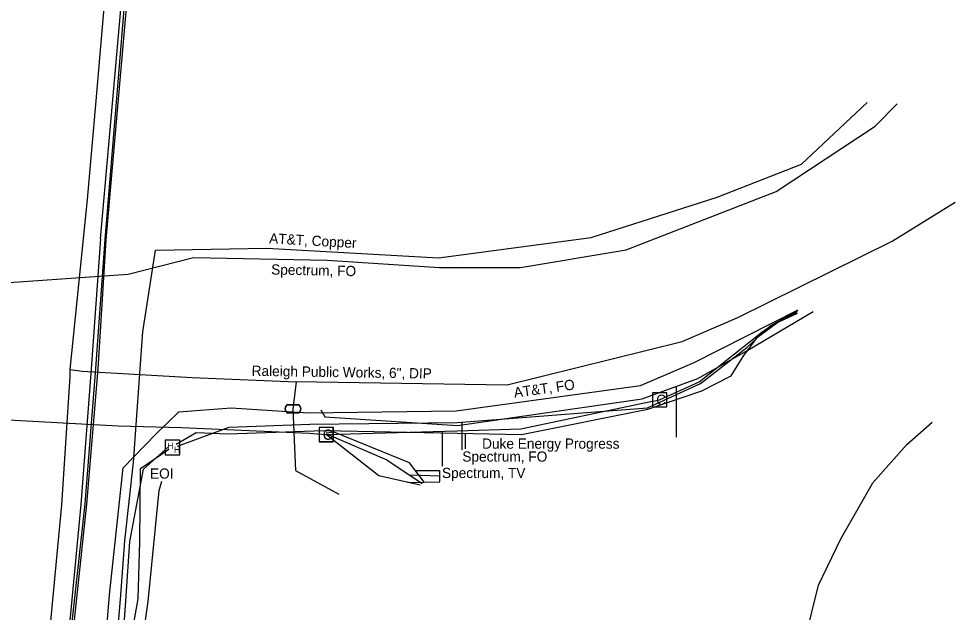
# Model space of a CAD drawing. Extents: x 2070721 to 2083039, y 729290 to 737883.
# Drawn here: x 2082364.3 to 2082731.1, y 736466.5 to 736699 of the extents above; entities that cross this region are included whole.
import ezdxf

# ---------------------------------------------------------------- set-up
doc = ezdxf.new("R2010")
doc.units = 0
for name, color, linetype in [('Cogo Default Point CELL', 7, 'Continuous'), ('Exist Utilities Gas UG Line SUE Cogo Point CELL', 7, 'Continuous'), ('Exist Utilities Gas UG Line SUE LOS B Cogo Comment', 7, 'Continuous'), ('Exist Utilities Gas UG Line SUE LOS B Cogo Number', 7, 'Continuous'), ('Exist Utilities Gas UG Line SUE LOS B Cogo Point CELL', 7, 'Continuous'), ('Exist Utilities Gas Valve CELL', 7, 'Continuous'), ('Exist Utilities Power Pole CELL', 7, 'Continuous'), ('Exist Utilities Telephone Hand Hole Cogo Elevation', 7, 'Continuous'), ('Exist Utilities Telephone Pedestal CELL', 7, 'Continuous'), ('Exist Utilities Telephone UG Cable Cogo Point CELL', 7, 'Continuous'), ('Exist Utilities Telephone UG Cable SUE LOS C Cogo Comment', 7, 'Continuous'), ('Exist Utilities Telephone UG FO Cogo Point CELL', 7, 'Continuous'), ('Exist Utilities TV Pedestal CELL', 7, 'Continuous'), ('Exist Utilities TV Pedestal Cogo Elevation', 7, 'Continuous'), ('Exist Utilities TV UG Cable Cogo Point CELL', 7, 'Continuous'), ('Exist Utilities TV UG Cable SUE LOS C Cogo Comment', 7, 'Continuous'), ('Exist Utilities TV UG Cable SUE LOS C Cogo Elevation', 7, 'Continuous'), ('Exist Utilities TV UG Cable SUE LOS C Cogo Point CELL', 7, 'Continuous'), ('Exist Utilities Water Manhole CELL', 7, 'Continuous'), ('Exist Utilities Water Meter CELL', 7, 'Continuous'), ('Exist Utilities Water Meter Cogo Number', 7, 'Continuous'), ('Exist Utilities Water UG Line SUE LOS B Cogo Elevation', 7, 'Continuous')]:
    doc.layers.add(name, color=color, linetype=linetype)

msp = doc.modelspace()

# ---------------------------------------------------------------- linework, layer by layer
at = {"layer": 'Cogo Default Point CELL'}
for p, q in [((2082615.26, 736549.71), (2082615.26, 736549.71)), ((2082484.65, 736536.03), (2082484.65, 736536.03)), ((2082484.7, 736536.09), (2082484.7, 736536.09))]:
    msp.add_line(p, q, dxfattribs=at)
for points in [[(2082612.49, 736546.94), (2082618.04, 736546.94), (2082618.04, 736552.48), (2082612.49, 736552.48), (2082612.49, 736546.94)], [(2082481.88, 736533.26), (2082487.43, 736533.26), (2082487.43, 736538.81), (2082481.88, 736538.81), (2082481.88, 736533.26)], [(2082481.93, 736533.32), (2082487.48, 736533.32), (2082487.48, 736538.86), (2082481.93, 736538.86), (2082481.93, 736533.32)]]:
    msp.add_lwpolyline(points, dxfattribs=at)
at = {"layer": 'Exist Utilities Gas UG Line SUE LOS B Cogo Number'}
for p, q in [((2082537.8, 736540.94), (2082537.8, 736530.14)), ((2082539.08, 736536.51), (2082539.08, 736530.49))]:
    msp.add_line(p, q, dxfattribs=at)
at = {"layer": 'Exist Utilities Gas Valve CELL'}
msp.add_line((2082621.8, 736554.96), (2082621.8, 736535.09), dxfattribs=at)
at = {"layer": 'Exist Utilities Power Pole CELL'}
for points in [[(2082396.3, 736612.75), (2082410.09, 736769.04), (2082413.73, 736812.06), (2082415.9, 736838.6), (2082420.43, 736883.01), (2082426.83, 736940.19), (2082430.34, 736980.56), (2082434.54, 737015.35), (2082440.98, 737055.09)], [(2082398.47, 736612.36), (2082412.17, 736768.95), (2082414.49, 736785.54), (2082418.32, 736838.61), (2082422.49, 736882.86), (2082432.87, 736980.11), (2082434.6, 737016.15), (2082441.99, 737054.65)], [(2082396.3, 736612.75), (2082392.62, 736561.83), (2082388.6, 736508.73), (2082382.17, 736441.21), (2082376.53, 736380.02), (2082370.92, 736297.49), (2082367.41, 736251.8), (2082369.98, 736249.96), (2082368.85, 736250.78)], [(2082370.04, 736251.07), (2082373.38, 736297.59), (2082378.96, 736379.81), (2082383.81, 736441.35), (2082390.88, 736508.81), (2082395.35, 736561.8), (2082398.47, 736612.36)]]:
    msp.add_lwpolyline(points, dxfattribs=at)
at = {"layer": 'Exist Utilities Telephone UG Cable Cogo Point CELL'}
msp.add_line((2082424.54, 736531.03), (2082424.54, 736531.03), dxfattribs=at)
msp.add_lwpolyline([(2082421.67, 736528.16), (2082427.42, 736528.16), (2082427.42, 736533.91), (2082421.67, 736533.91), (2082421.67, 736528.16)], dxfattribs=at)
at = {"layer": 'Exist Utilities Telephone UG Cable SUE LOS C Cogo Comment'}
msp.add_lwpolyline([(2082395.72, 736292.86), (2082399.83, 736311.96), (2082400.03, 736311.89), (2082404.85, 736370.66), (2082409.06, 736429.49), (2082414.93, 736470.65), (2082419.29, 736514.19), (2082420.3, 736517.77)], dxfattribs=at)
at = {"layer": 'Exist Utilities Telephone UG FO Cogo Point CELL'}
msp.add_line((2082471.67, 736546.21), (2082471.67, 736546.21), dxfattribs=at)
for points in [[(2082469.63, 736547.91), (2082473.71, 736547.91)], [(2082469.63, 736547.77), (2082473.71, 736547.77)], [(2082473.71, 736544.65), (2082469.61, 736544.65)], [(2082473.71, 736544.51), (2082469.61, 736544.51)]]:
    msp.add_lwpolyline(points, dxfattribs=at)
for centre, radius, start, end in [((2082470.36, 736546.2), 1.86, 113.178, 245.9794), ((2082470.37, 736546.2), 1.73, 115.3009, 243.7824), ((2082472.96, 736546.21), 1.86, 293.6483, 66.3084), ((2082472.97, 736546.21), 1.73, 295.1272, 64.8728)]:
    msp.add_arc(centre, radius, start, end, dxfattribs=at)
at = {"layer": 'Exist Utilities TV Pedestal CELL'}
for points in [[(2082425.9, 736532.27), (2082433.71, 736536.84), (2082446.22, 736536.42), (2082483.71, 736537.72), (2082535.95, 736536.62), (2082561.21, 736536.1), (2082610.64, 736546), (2082631.79, 736553.16), (2082643.29, 736559.15), (2082648.05, 736566.62), (2082653.66, 736574.26), (2082661.61, 736580.11), (2082669.14, 736584.07)], [(2082426.4, 736531.55), (2082446.63, 736539.04), (2082478.25, 736540.13), (2082535.97, 736540.82), (2082610.47, 736546.5), (2082631.23, 736556.05), (2082649.4, 736570.19), (2082658.63, 736578.68), (2082669.27, 736583.69)], [(2082383.39, 736263.77), (2082384.87, 736281.05), (2082388.71, 736311.38), (2082396.25, 736370.54), (2082403.33, 736430.4), (2082406.33, 736472.77), (2082407.72, 736494.25), (2082413.13, 736522.51), (2082423.07, 736531.36)], [(2082385.03, 736263.7), (2082391.12, 736281.95), (2082396.82, 736312.11), (2082398.55, 736370.94), (2082403.55, 736430), (2082411.08, 736471.72), (2082411.73, 736494.17), (2082412, 736522.79), (2082423.09, 736530.34)]]:
    msp.add_lwpolyline(points, dxfattribs=at)
at = {"layer": 'Exist Utilities TV Pedestal Cogo Elevation'}
for points in [[(2082384.35, 736558.86), (2082384.46, 736561.59), (2082391.2, 736628.12), (2082394.55, 736666.82), (2082398.88, 736717.07), (2082400.72, 736736.91)], [(2082472.81, 736556.82), (2082555.61, 736555.54), (2082624.05, 736572.52), (2082645.91, 736581.87), (2082706.38, 736611.81), (2082731.06, 736627.13)], [(2082359.3, 736290.13), (2082359.45, 736292.32), (2082374.67, 736439.46), (2082381.09, 736508.57), (2082384.35, 736558.86)], [(2082384.46, 736561.59), (2082389.12, 736560.96), (2082432.21, 736558.41), (2082472.93, 736556.77)], [(2082472.93, 736556.77), (2082472.27, 736551.43), (2082471.61, 736546.09), (2082472.7, 736521.96), (2082489.65, 736512.8)]]:
    msp.add_lwpolyline(points, dxfattribs=at)
at = {"layer": 'Exist Utilities TV UG Cable Cogo Point CELL'}
msp.add_lwpolyline([(2082392.88, 736263.89), (2082382.27, 736265.88), (2082385.19, 736281.09), (2082389.11, 736311.29), (2082396.78, 736370.29), (2082400.63, 736429.15), (2082404.26, 736473.32), (2082405.87, 736494.42), (2082409.26, 736525.23), (2082412.82, 736576.27), (2082417.8, 736608.3), (2082461.47, 736609.04), (2082528.72, 736605.28), (2082588.4, 736613.3), (2082637.77, 736629.11), (2082670.84, 736641.95), (2082696.51, 736666.16)], dxfattribs=at)
at = {"layer": 'Exist Utilities TV UG Cable SUE LOS C Cogo Comment'}
for points in [[(2082482.56, 736545.79), (2082484.21, 736542.97), (2082536.06, 736539.61), (2082608.47, 736550.06), (2082630.23, 736558.05), (2082649.11, 736568.73), (2082675.35, 736584.3)], [(2082633.41, 736326.82), (2082635.39, 736331.76), (2082647.25, 736364.29), (2082654.64, 736387.64), (2082662.17, 736415.15), (2082677.46, 736477.1), (2082686.22, 736495.26), (2082698.83, 736517.21), (2082712.08, 736532.18), (2082721.96, 736540.93)]]:
    msp.add_lwpolyline(points, dxfattribs=at)
at = {"layer": 'Exist Utilities TV UG Cable SUE LOS C Cogo Elevation'}
for points in [[(2082346.94, 736593.86), (2082360.72, 736589.21), (2082357.72, 736541.97), (2082403.21, 736539.49), (2082428.03, 736538.87), (2082478.07, 736536.61), (2082484.59, 736536.15), (2082535.98, 736537.5), (2082560.91, 736538.33), (2082609.93, 736548.58), (2082615.28, 736549.68), (2082630.73, 736556.71), (2082655.26, 736576.14), (2082659.68, 736579.26), (2082669.26, 736584.45)], [(2082523.24, 736517.33), (2082517.33, 736525), (2082487.79, 736537.04), (2082484.69, 736536.67)], [(2082484.78, 736536.42), (2082508.4, 736526.14), (2082522.29, 736516.92)], [(2082521.51, 736516.25), (2082505.36, 736519.92), (2082484.78, 736536.03)]]:
    msp.add_lwpolyline(points, dxfattribs=at)
at = {"layer": 'Exist Utilities TV UG Cable SUE LOS C Cogo Point CELL'}
for points in [[(2082398.1, 736612.48), (2082411.1, 736769.26), (2082413.2, 736785.84), (2082417.08, 736838.79), (2082421.4, 736882.93), (2082431.06, 736980.24), (2082434.68, 737016.11), (2082441.24, 737055.15)], [(2082369.85, 736250.96), (2082372.63, 736297.63), (2082378.59, 736379.94), (2082382.86, 736441.28), (2082390.24, 736508.9), (2082394.52, 736561.91), (2082398.1, 736612.48)], [(2082380.42, 736270.25), (2082381.12, 736283.15), (2082384.63, 736311.5), (2082391.98, 736371.16), (2082396.29, 736430.22), (2082399.86, 736473.26), (2082405.23, 736523.1), (2082417.88, 736536.05), (2082427.03, 736545.03), (2082447.47, 736546.52), (2082477.66, 736544.64), (2082535.53, 736545.32), (2082607.76, 736555.33), (2082628.77, 736564.28), (2082669.56, 736584.92)]]:
    msp.add_lwpolyline(points, dxfattribs=at)
at = {"layer": 'Exist Utilities Water Manhole CELL'}
for p, q in [((2082530.08, 736537.27), (2082530.08, 736523.74)), ((2082519.78, 736522.06), (2082529.16, 736522.06))]:
    msp.add_line(p, q, dxfattribs=at)
for points in [[(2082517.8, 736520.25), (2082529.16, 736519.88), (2082529.16, 736522.04)], [(2082516.56, 736517.37), (2082529.16, 736517.56), (2082529.16, 736519.84)]]:
    msp.add_lwpolyline(points, dxfattribs=at)
at = {"layer": 'Exist Utilities Water UG Line SUE LOS B Cogo Elevation'}
msp.add_lwpolyline([(2082347.36, 736594.7), (2082407.12, 736598.92), (2082432.73, 736605.4), (2082485.1, 736604.34), (2082529.04, 736601.5), (2082560.83, 736601.5), (2082602.16, 736608.48), (2082660.87, 736631.23), (2082699.66, 736656.83), (2082708.35, 736665.58)], dxfattribs=at)

# ---------------------------------------------------------------- texts
at = {"layer": 'Cogo Default Point CELL'}
for p in [(2082613.95, 736547.71), (2082483.34, 736534.03), (2082483.39, 736534.09)]:
    msp.add_text('C', height=4, dxfattribs=at).set_placement(p)
at = {"layer": 'Exist Utilities Gas UG Line SUE Cogo Point CELL'}
msp.add_text('Raleigh Public Works, 6", DIP ', height=4, rotation=359.1143, dxfattribs=at).set_placement((2082455.47, 736559.09))
at = {"layer": 'Exist Utilities Gas UG Line SUE LOS B Cogo Comment'}
msp.add_text('AT&T, FO', height=4, rotation=7.8901, dxfattribs=at).set_placement((2082558.43, 736550.51))
at = {"layer": 'Exist Utilities Gas UG Line SUE LOS B Cogo Point CELL'}
msp.add_text('Spectrum, FO ', height=4, dxfattribs=at).set_placement((2082538, 736525.47))
at = {"layer": 'Exist Utilities Telephone Hand Hole Cogo Elevation'}
msp.add_text('Spectrum, TV ', height=4, dxfattribs=at).set_placement((2082530.03, 736519.05))
at = {"layer": 'Exist Utilities Telephone Pedestal CELL'}
msp.add_text('Spectrum, FO ', height=4, rotation=358.8396, dxfattribs=at).set_placement((2082463.09, 736598.78))
at = {"layer": 'Exist Utilities Telephone UG Cable Cogo Point CELL'}
for p in [(2082422.45, 736530.38), (2082425.03, 736528.92)]:
    msp.add_text('H', height=2.5, dxfattribs=at).set_placement(p)
at = {"layer": 'Exist Utilities Telephone UG Cable SUE LOS C Cogo Comment'}
msp.add_text('EOI', height=4, dxfattribs=at).set_placement((2082415.68, 736518.81))
at = {"layer": 'Exist Utilities Water Meter CELL'}
msp.add_text('Duke Energy Progress', height=4, dxfattribs=at).set_placement((2082545.74, 736530.54))
at = {"layer": 'Exist Utilities Water Meter Cogo Number'}
msp.add_text('AT&T, Copper', height=4, rotation=356.7999, dxfattribs=at).set_placement((2082462.29, 736611))

doc.saveas('drawing.dxf')
